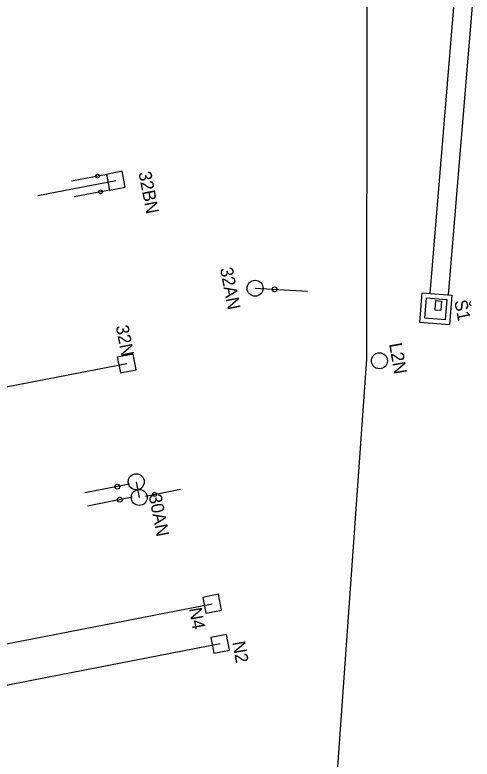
# Model space of a CAD drawing. Extents: x -545258 to -544992, y -1122311 to -1121664.
# Drawn here: x -545140.8 to -545096.2, y -1122127.2 to -1122054.6 of the extents above; entities that cross this region are included whole.
import ezdxf

# ---------------------------------------------------------------- set-up
doc = ezdxf.new("R2010")
doc.units = 0
for name, color, linetype in [('SO 18-01-01_3', 7, 'Continuous'), ('SO 18-01-01_4', 7, 'Continuous'), ('SO18-15-08_def', 7, 'Continuous')]:
    doc.layers.add(name, color=color, linetype=linetype)

msp = doc.modelspace()

# ---------------------------------------------------------------- linework, layer by layer
at = {"layer": 'SO 18-01-01_3'}
for p, q in [((-545131.82, -1122070.164), (-545135.23, -1122070.829)), ((-545130.905, -1122070.78), (-545138.529, -1122072.266)), ((-545131.521, -1122071.695), (-545134.931, -1122072.36)), ((-545117.323, -1122081.282), (-545112.207, -1122081.551)), ((-545160.59, -1122094.603), (-545129.852, -1122088.611)), ((-545129.567, -1122100.41), (-545133.928, -1122101.26)), ((-545128.921, -1122100.163), (-545128.623, -1122101.695)), ((-545128.012, -1122101.575), (-545124.603, -1122100.903)), ((-545129.315, -1122101.685), (-545133.679, -1122102.536)), ((-545174.491, -1122122.395), (-545121.511, -1122112.067)), ((-545120.746, -1122115.994), (-545173.725, -1122126.321))]:
    msp.add_line(p, q, dxfattribs=at)
for points in [[(-545131.82, -1122070.164), (-545131.521, -1122071.695), (-545129.99, -1122071.397), (-545130.288, -1122069.865)], [(-545130.767, -1122087.995), (-545130.468, -1122089.526), (-545128.937, -1122089.228), (-545129.236, -1122087.697)], [(-545122.127, -1122112.982), (-545120.596, -1122112.684), (-545120.895, -1122111.153), (-545122.426, -1122111.451)], [(-545121.362, -1122116.908), (-545119.831, -1122116.61), (-545120.129, -1122115.079), (-545121.661, -1122115.377)]]:
    msp.add_lwpolyline(points, close=True, dxfattribs=at)
for centre, radius in [((-545132.701, -1122070.336), 0.187), ((-545132.403, -1122071.867), 0.187), ((-545117.323, -1122081.282), 0.78), ((-545115.423, -1122081.382), 0.234), ((-545105.201, -1122088.358), 0.78), ((-545128.923, -1122100.165), 0.78), ((-545130.767, -1122100.643), 0.234), ((-545128.624, -1122101.696), 0.78), ((-545127.13, -1122101.401), 0.187), ((-545130.518, -1122101.919), 0.234)]:
    msp.add_circle(centre, radius, dxfattribs=at)
at = {"layer": 'SO 18-01-01_4'}
msp.add_lwpolyline([(-545102.793, -1122250.491), (-545106.116, -1122208.618), (-545109.928, -1122137.596), (-545106.412, -1122088.188), (-545106.367, -1122023.596), (-545108.703, -1121978.559), (-545127.424, -1121916.593), (-545139.015, -1121857.213), (-545147.82, -1121812.064), (-545159.299, -1121753.172), (-545170.035, -1121688.35), (-545174.127, -1121676.058)], dxfattribs=at)
msp.add_circle((-545105.201, -1122088.358), 0.78, dxfattribs=at)
at = {"layer": 'SO18-15-08_def'}
for p, q in [((-545100.261, -1122081.789), (-545097.931, -1122053.829)), ((-545096.159, -1122053.706), (-545098.5, -1122081.932)), ((-545101.264, -1122084.618), (-545101.03, -1122081.727)), ((-545101.03, -1122081.727), (-545098.139, -1122081.961)), ((-545100.779, -1122084.206), (-545100.617, -1122082.212)), ((-545100.617, -1122082.212), (-545098.624, -1122082.373)), ((-545099.737, -1122082.484), (-545099.809, -1122083.381)), ((-545099.737, -1122082.484), (-545099.138, -1122082.532)), ((-545099.138, -1122082.532), (-545099.211, -1122083.429)), ((-545098.624, -1122082.373), (-545098.785, -1122084.367)), ((-545098.139, -1122081.961), (-545098.373, -1122084.852)), ((-545099.809, -1122083.381), (-545099.211, -1122083.429)), ((-545098.373, -1122084.852), (-545101.264, -1122084.618)), ((-545098.785, -1122084.367), (-545100.779, -1122084.206))]:
    msp.add_line(p, q, dxfattribs=at)

# ---------------------------------------------------------------- texts
at = {"layer": 'SO 18-01-01_3'}
for s, rotation, p in [('32BN', 280.95707, (-545128.707, -1122069.995)), ('32AN', 280.95707, (-545120.757, -1122079.36)), ('32N', 280.95707, (-545130.924, -1122084.992)), ('30AN', 281.04583, (-545127.71, -1122101.499)), ('N4', 280.00289, (-545123.782, -1122112.553)), ('N2', 279.94918, (-545119.546, -1122115.828))]:
    msp.add_text(s, height=1.25, rotation=rotation, dxfattribs=at).set_placement(p)
at = {"layer": 'SO 18-01-01_4'}
msp.add_text('L2N', height=1.25, rotation=280.00289, dxfattribs=at).set_placement((-545104.261, -1122086.719))
at = {"layer": 'SO18-15-08_def'}
msp.add_text('Š1', height=1.25, rotation=281.02812, dxfattribs=at).set_placement((-545097.903, -1122082.527))

doc.saveas('drawing.dxf')
